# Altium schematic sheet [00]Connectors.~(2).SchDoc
size A4; SheetNumber: 5; SheetTotal: 5
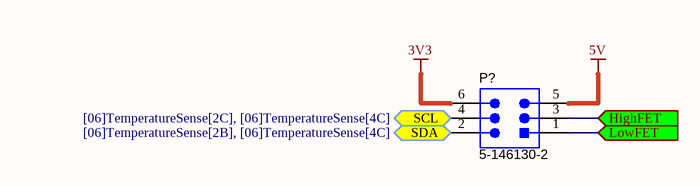
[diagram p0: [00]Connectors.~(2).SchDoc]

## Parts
P?  5-146130-2  [TECO-5-146130-2_V]

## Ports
HighFET (in, see [05]BuckConverter[1A], [05]BuckConverter[1C]), LowFET (in, see [05]BuckConverter[1A], [05]BuckConverter[1C]), SCL (bidir, see [06]TemperatureSense[2C], [06]TemperatureSense[4C]), SDA (bidir, see [06]TemperatureSense[2B], [06]TemperatureSense[4C])

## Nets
3V3: P?.6
5V: P?.5
HighFET: P?.3 ; port HighFET
LowFET: P?.1 ; port LowFET
SCL: P?.4 ; port SCL
SDA: P?.2 ; port SDA

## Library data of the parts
P? = CMP-002-00018-2: Male Header, Pitch 2.54 mm, 2 x 3 Position, Height 8.13 mm, -65 to 125 degC, RoHS, Tube; Manufacturer: TE Connectivity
